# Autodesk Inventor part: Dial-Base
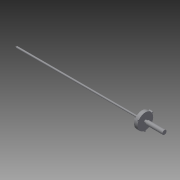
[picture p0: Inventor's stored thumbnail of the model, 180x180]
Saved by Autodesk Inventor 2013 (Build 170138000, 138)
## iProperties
Shininess: 64.0
Length Units: 11272
Angle Units: 11279
Time Units: 11290
Mass Units: 11286
Length Display Precision: 3
Angle Display Precision: 2
Compacted: True
Created: 2001-11
Part Number: Dial-Base
Document SubType Name: Modeling
Designer: Autodesk, Inc.
Mass: 1.78334 g
Surface Area: 19.6041 cm^2
Volume: 1.78334 cm^3
Density: 1 g/cm^3
Material: Generic
Density: 0.0
Volumn: 0.0
Area: 0.0
PropertySet Name: Model Information
Control State: 0
Master: False
Checked Out: False
Author: Autodesk, Inc.
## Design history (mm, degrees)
sketch "Sketch1"
  geometry: L1 (150.134, 1.855)-(150.134, 2.363); L2 (147.848, 1.601)-(149.88, 1.601); L3 (147.594, 1.855)-(147.594, 8.903); L4 (143.657, 8.903)-(147.594, 8.903); L5 (143.657, 0.979)-(143.657, 8.903); L6 (1.649, 0.979)-(143.657, 0.979); L7 (0, 0)-(1.649, 0.979); L8 (169.311, 0)-(169.311, 2.363); L9 (150.134, 2.363)-(169.311, 2.363); L10 (0, 0)-(169.311, 0); A1 r 0.254 centre (149.88, 1.855) between (149.88, 1.601) and (150.134, 1.855); A2 r 0.254 centre (147.848, 1.855) between (147.594, 1.855) and (147.848, 1.601); 1 further point
  constraints: 20 end point, 4 horizontal, 4 point on circle, 4 tangent, 4 vertical, 2 centre point, 1 coincident, 1 equal radius, 1 parallel
  dimensions: "d11" = 1.95865 diameter of L6 L10; "d12" = 17.80607 diameter of L4 L10; "d13" = 4.72507 diameter of L9 L10; "d14" = 19.177 distance of L1.end L8.end; "d15" = 0.254 radius of A1; "d16" = 2.54 distance between parallel lines of L1 L3; "d17" = 3.937 distance of L4.start L3.end; "d18" = 142.00729 distance of L6.start L5.start; "d19" = 30.6993 deg angle of L10 L7; "d20" = 3.20107 diameter of L2 L10
revolve "RevolutionFull1" sketch "Sketch1" stored, may be unused: angle "d0" = 360 deg
sketch "Sketch2"
  geometry: L1 (9.094, 4.56)-(7.989, 3.93); L2 (8.551, 5.511)-(7.446, 4.881); L3 (0, -12.464)-(0, 12.464) reference; A1 r 8.903 centre (0, 0) between (7.446, 4.881) and (7.989, 3.93) reference; A2 r 10.173 centre (0, 0) between (9.094, 4.56) and (8.551, 5.511)
  constraints: 4 end point, 4 point on circle, 2 parallel, 1 centre point, 1 coincident
  dimensions: "d21" = 60.2814 deg angle of L2 L3; "d23" = 1.09507 distance between parallel lines of L1 L2; "d24" = 1.27215 distance of L2.start L2.end
extrude "ExtrusionToPlane1" join sketch "Sketch2" stored distance "d5" = 3.302; taper "d6" = 0 deg
pattern_circular "Circular Pattern1" dims angle "d27" = 360 deg
body "Solid1"
other parameters: "d1" = 0, "d2" = 0, "d3" = 0, "d4" = 0
